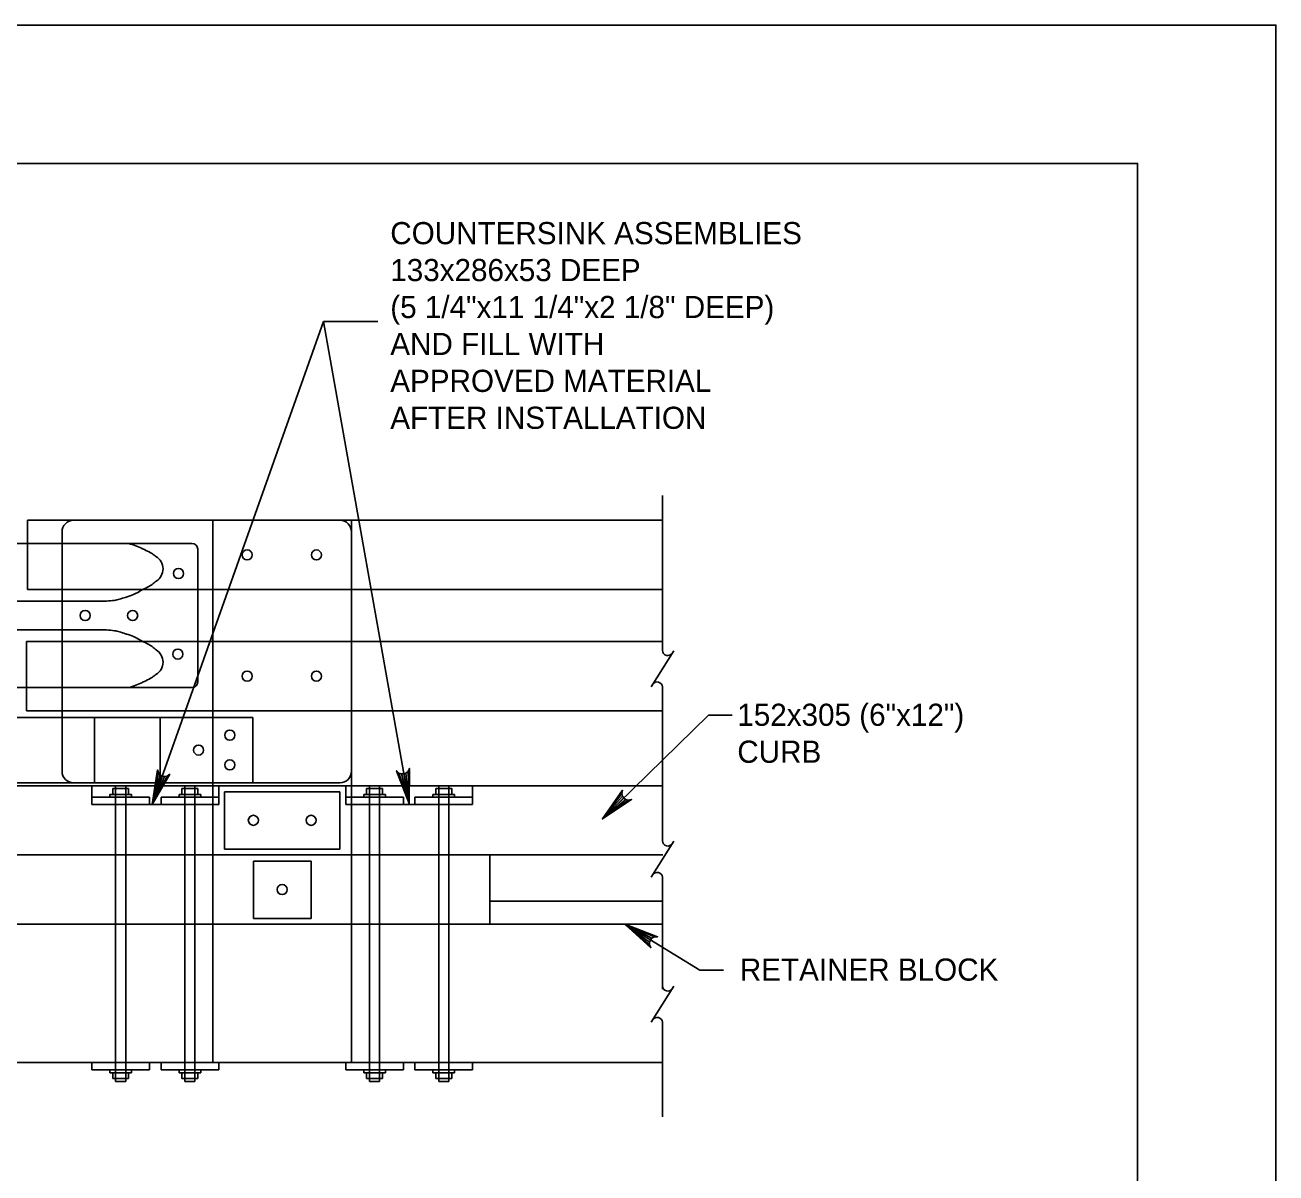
# Model space of a CAD drawing. Extents: x 0 to 36.3, y -66 to 0.
# Drawn here: x 27.22 to 34, y -6.22 to 0 of the extents above; entities that cross this region are included whole.
import ezdxf

# ---------------------------------------------------------------- set-up
doc = ezdxf.new("R2010")
doc.units = 0
for name, color, linetype in [('1', 7, 'Continuous'), ('2', 7, 'Continuous'), ('3', 7, 'Continuous'), ('52', 7, 'Continuous'), ('62', 7, 'Continuous'), ('63', 7, 'Continuous')]:
    doc.layers.add(name, color=color, linetype=linetype)

msp = doc.modelspace()

# ---------------------------------------------------------------- linework, layer by layer
at = {"layer": '1'}
msp.add_lwpolyline([(1.75, -21.25), (33.25, -21.25), (33.25, -0.75), (1.75, -0.75)], close=True, dxfattribs=at)
at = {"layer": '2'}
for p, q in [((30.6771, -2.5474), (30.6771, -3.3866)), ((27.2378, -2.6827), (29.2847, -2.6827)), ((28.243, -2.6827), (28.243, -3.0577)), ((28.993, -2.6827), (28.993, -3.0577)), ((29.2847, -2.6827), (30.6789, -2.6827)), ((27.4253, -2.7452), (27.4253, -3.5889)), ((26.2853, -2.8077), (28.1291, -2.8077)), ((27.2378, -2.8077), (27.2378, -3.0577)), ((28.1603, -2.839), (28.1603, -3.5577)), ((28.993, -3.0577), (27.2378, -3.0577)), ((28.243, -3.0577), (28.243, -3.3389)), ((28.993, -3.0577), (28.993, -3.3389)), ((28.993, -3.0577), (30.6789, -3.0577)), ((24.7539, -3.1202), (27.667, -3.1202)), ((24.7335, -3.2764), (27.667, -3.2764)), ((28.993, -3.3389), (27.2335, -3.3389)), ((27.2335, -3.5889), (27.2335, -3.3389)), ((28.243, -3.3389), (28.243, -3.7139)), ((28.993, -3.3389), (28.993, -3.7139)), ((28.993, -3.3389), (30.6789, -3.3389)), ((30.7385, -3.3888), (30.6157, -3.5844)), ((24.7335, -3.5889), (28.1291, -3.5889)), ((27.2335, -3.5889), (27.2335, -3.7139)), ((27.4253, -3.5889), (27.4253, -4.0414)), ((30.677, -3.584), (30.677, -4.4181)), ((27.2335, -3.7139), (27.4253, -3.7139)), ((28.993, -3.7139), (27.4253, -3.7139)), ((28.243, -3.7139), (28.243, -4.2217)), ((28.993, -3.7139), (28.993, -4.2217)), ((28.993, -3.7139), (30.6789, -3.7139)), ((24.5044, -3.7502), (28.459, -3.7502)), ((28.993, -3.9997), (28.993, -4.1202)), ((24.5044, -4.1039), (28.9305, -4.1039)), ((25.5295, -4.1202), (30.6789, -4.1202)), ((26.7773, -4.1202), (30.4587, -4.1202)), ((27.5867, -4.1202), (27.5867, -4.2217)), ((27.7156, -4.1202), (27.7703, -4.1202)), ((27.7156, -4.1202), (27.7156, -5.7217)), ((27.7703, -4.1202), (27.7703, -5.7217)), ((28.0906, -4.1202), (28.1453, -4.1202)), ((28.0906, -4.1202), (28.0906, -5.7217)), ((28.1453, -4.1202), (28.1453, -5.7217)), ((28.243, -4.1039), (28.243, -4.1202)), ((28.2742, -4.1202), (28.2742, -4.2217)), ((28.9617, -4.1202), (28.9617, -4.2217)), ((28.993, -4.1039), (28.993, -4.1697)), ((29.0906, -4.1202), (29.1453, -4.1202)), ((29.0906, -4.1202), (29.0906, -5.7217)), ((29.1453, -4.1202), (29.1453, -5.7217)), ((29.4656, -4.1202), (29.5203, -4.1202)), ((29.4656, -4.1202), (29.4656, -5.7217)), ((29.5203, -4.1202), (29.5203, -5.7217)), ((29.6492, -4.1202), (29.6492, -4.2217)), ((27.8992, -4.1827), (27.5867, -4.1827)), ((27.6843, -4.167), (27.6843, -4.1827)), ((27.6843, -4.167), (27.8015, -4.167)), ((27.6999, -4.1357), (27.6999, -4.167)), ((27.6999, -4.1357), (27.7859, -4.1357)), ((27.7859, -4.1357), (27.7859, -4.167)), ((27.8015, -4.167), (27.8015, -4.1827)), ((27.8992, -4.1827), (27.8992, -4.2217)), ((28.2742, -4.1827), (27.9617, -4.1827)), ((27.9617, -4.1827), (27.9617, -4.2217)), ((28.0593, -4.167), (28.0593, -4.1827)), ((28.0593, -4.167), (28.1765, -4.167)), ((28.0749, -4.1357), (28.1609, -4.1357)), ((28.0749, -4.1357), (28.0749, -4.167)), ((28.1609, -4.1357), (28.1609, -4.167)), ((28.1765, -4.167), (28.1765, -4.1827)), ((28.3055, -4.1537), (28.9305, -4.1537)), ((28.3055, -4.1537), (28.3055, -4.4639)), ((28.3055, -4.1538), (28.9305, -4.1538)), ((28.9305, -4.1537), (28.9305, -4.4639)), ((29.2742, -4.1827), (28.9617, -4.1827)), ((29.0593, -4.167), (29.0593, -4.1827)), ((29.0593, -4.167), (29.1765, -4.167)), ((29.0749, -4.1357), (29.1609, -4.1357)), ((29.0749, -4.1357), (29.0749, -4.167)), ((29.1609, -4.1357), (29.1609, -4.167)), ((29.1765, -4.167), (29.1765, -4.1827)), ((29.2742, -4.1827), (29.2742, -4.2217)), ((29.6492, -4.1827), (29.3367, -4.1827)), ((29.3367, -4.1827), (29.3367, -4.2217)), ((29.4343, -4.167), (29.4343, -4.1827)), ((29.4343, -4.167), (29.5515, -4.167)), ((29.4499, -4.1357), (29.5359, -4.1357)), ((29.4499, -4.1357), (29.4499, -4.167)), ((29.5359, -4.1357), (29.5359, -4.167)), ((29.5515, -4.167), (29.5515, -4.1827)), ((27.5867, -4.2217), (28.2742, -4.2217)), ((28.243, -4.2217), (28.243, -5.6201)), ((28.9617, -4.2217), (29.6492, -4.2217)), ((28.993, -4.2217), (28.993, -5.6201)), ((28.3055, -4.4639), (28.9305, -4.4639)), ((30.7385, -4.4203), (30.6157, -4.6159)), ((25.5295, -4.4952), (30.6789, -4.4952)), ((28.4617, -4.5287), (28.4617, -4.8389)), ((28.4617, -4.5287), (28.7742, -4.5287)), ((28.7742, -4.5287), (28.7742, -4.8389)), ((29.743, -4.4952), (29.743, -4.8702)), ((30.677, -4.6156), (30.677, -5.2228)), ((29.743, -4.7452), (30.6789, -4.7452)), ((25.5295, -4.8702), (30.6789, -4.8702)), ((28.4617, -4.8389), (28.7742, -4.8389)), ((30.7385, -5.2059), (30.6157, -5.4015)), ((30.677, -5.4023), (30.677, -5.9131)), ((25.5295, -5.6201), (30.6789, -5.6201)), ((27.5867, -5.6592), (27.5867, -5.6201)), ((27.8992, -5.6592), (27.8992, -5.6201)), ((27.9617, -5.6592), (27.9617, -5.6201)), ((28.2742, -5.6592), (28.2742, -5.6201)), ((28.9617, -5.6592), (28.9617, -5.6201)), ((29.2742, -5.6592), (29.2742, -5.6201)), ((29.3367, -5.6592), (29.3367, -5.6201)), ((29.6492, -5.6592), (29.6492, -5.6201)), ((27.8992, -5.6592), (27.5867, -5.6592)), ((27.6843, -5.6748), (27.6843, -5.6592)), ((27.6843, -5.6748), (27.8015, -5.6748)), ((27.6999, -5.7061), (27.6999, -5.6748)), ((27.7859, -5.7061), (27.7859, -5.6748)), ((27.8015, -5.6748), (27.8015, -5.6592)), ((28.2742, -5.6592), (27.9617, -5.6592)), ((28.0593, -5.6748), (28.0593, -5.6592)), ((28.0593, -5.6748), (28.1765, -5.6748)), ((28.0749, -5.7061), (28.0749, -5.6748)), ((28.1609, -5.7061), (28.1609, -5.6748)), ((28.1765, -5.6748), (28.1765, -5.6592)), ((29.2742, -5.6592), (28.9617, -5.6592)), ((29.0593, -5.6748), (29.0593, -5.6592)), ((29.0593, -5.6748), (29.1765, -5.6748)), ((29.0749, -5.7061), (29.0749, -5.6748)), ((29.1609, -5.7061), (29.1609, -5.6748)), ((29.1765, -5.6748), (29.1765, -5.6592)), ((29.6492, -5.6592), (29.3367, -5.6592)), ((29.4343, -5.6748), (29.4343, -5.6592)), ((29.4343, -5.6748), (29.5515, -5.6748)), ((29.4499, -5.7061), (29.4499, -5.6748)), ((29.5359, -5.7061), (29.5359, -5.6748)), ((29.5515, -5.6748), (29.5515, -5.6592)), ((27.6999, -5.7061), (27.7859, -5.7061)), ((27.7156, -5.7217), (27.7703, -5.7217)), ((28.0749, -5.7061), (28.1609, -5.7061)), ((28.0906, -5.7217), (28.1453, -5.7217)), ((29.0749, -5.7061), (29.1609, -5.7061)), ((29.0906, -5.7217), (29.1453, -5.7217)), ((29.4499, -5.7061), (29.5359, -5.7061)), ((29.4656, -5.7217), (29.5203, -5.7217))]:
    msp.add_line(p, q, dxfattribs=at)
for centre in [(28.4279, -2.8702), (28.8031, -2.8702), (28.0561, -2.9709), (27.5508, -3.1983), (27.8078, -3.1983), (28.0529, -3.4071), (28.4279, -3.5265), (28.8031, -3.5265), (28.3342, -3.8464), (28.165, -3.927), (28.3342, -4.0077), (28.4617, -4.3076), (28.7742, -4.3076), (28.618, -4.6826)]:
    msp.add_circle(centre, 0.0273, dxfattribs=at)
for centre, radius, start, end in [((27.4878, -2.7452), 0.0625, 90, 180), ((27.5337, -3.6302), 0.8602, 71.50655, 72.97663), ((27.756, -2.9656), 0.1594, 68.09066, 71.50655), ((25.7728, -7.8966), 5.4742, 67.68511, 68.09066), ((27.6609, -3.2963), 0.5016, 66.34532, 67.68511), ((27.7801, -3.0241), 0.2044, 63.42506, 66.34532), ((26.6682, -5.2469), 2.6898, 62.62019, 63.42506), ((28.129, -2.839), 0.0312, 0, 90), ((27.8681, -2.9302), 0.0808, 54.67713, 62.62019), ((27.6988, -3.169), 0.3735, 50.98486, 54.67712), ((27.8948, -2.9456), 0.0775, 301.3851, 59.64679), ((12.0358, 26.154), 33.224, 298.47252, 298.525), ((27.8577, -2.9561), 0.092, 298.525, 306.88177), ((27.6621, -2.6954), 0.4179, 306.88177, 310.79926), ((27.6474, -2.6951), 0.4255, 272.64288, 278.36698), ((27.6827, -2.9355), 0.1825, 278.36698, 287.11147), ((25.448, 4.3233), 7.7775, 287.11147, 287.36106), ((27.6895, -2.8462), 0.2658, 287.36106, 288.71113), ((27.2816, -1.6421), 1.5372, 288.71113, 290.23288), ((27.7944, -3.0333), 0.0545, 290.23288, 298.32146), ((26.9595, -1.4842), 1.8143, 298.32146, 298.75012), ((32.5137, -11.608), 9.733, 118.56505, 118.75012), ((32.9699, -12.4459), 10.6871, 118.47252, 118.56505), ((27.6474, -3.7015), 0.4255, 81.63302, 87.35713), ((27.6827, -3.4611), 0.1825, 72.88853, 81.63302), ((25.448, -10.7199), 7.7775, 72.63894, 72.88853), ((27.6895, -3.5504), 0.2658, 71.28887, 72.63894), ((27.2816, -4.7546), 1.5372, 69.76712, 71.28887), ((27.7944, -3.3634), 0.0545, 61.67854, 69.76712), ((26.9595, -4.9125), 1.8143, 61.24988, 61.67854), ((32.5137, 5.2113), 9.733, 241.24988, 241.43495), ((32.9699, 6.0493), 10.6871, 241.43495, 241.52748), ((12.0358, -32.5506), 33.224, 61.475, 61.52748), ((27.8577, -3.4405), 0.092, 53.11823, 61.475), ((27.6621, -3.7012), 0.4179, 49.20074, 53.11823), ((27.8948, -3.451), 0.0775, 300.35321, 58.61491), ((30.7059, -3.3866), 0.0289, 180, 330), ((27.6988, -3.2276), 0.3735, 305.32288, 309.01514), ((27.5337, -2.7665), 0.8602, 287.02337, 288.49345), ((27.756, -3.4311), 0.1594, 288.49345, 291.90934), ((25.7728, 1.4999), 5.4742, 291.90934, 292.31489), ((27.6609, -3.1003), 0.5016, 292.31489, 293.65468), ((27.7801, -3.3726), 0.2044, 293.65468, 296.57494), ((26.6682, -1.1498), 2.6898, 296.57494, 297.37981), ((27.8681, -3.4665), 0.0808, 297.37981, 305.32288), ((28.129, -3.5577), 0.0312, 270, 0), ((30.6483, -3.5867), 0.0289, 5.32859, 147.86724), ((27.4878, -4.0414), 0.0625, 180, 270), ((28.9304, -4.0414), 0.0625, 270, 0), ((30.7059, -4.4181), 0.0289, 180, 330), ((30.6483, -4.6182), 0.0289, 5.32859, 147.86724), ((30.7059, -5.2037), 0.0289, 180, 330), ((30.6483, -5.4037), 0.0289, 5.32859, 147.86724)]:
    msp.add_arc(centre, radius, start, end, dxfattribs=at)
at = {"layer": '3'}
for p, q in [((28.8409, -1.606), (27.9137, -4.2217)), ((28.8409, -1.606), (29.135, -1.606)), ((28.8409, -1.606), (29.3046, -4.2164)), ((27.2378, -2.6827), (27.2378, -2.8077)), ((28.993, -4.0414), (28.993, -2.7452)), ((27.601, -4.1039), (27.601, -3.7502)), ((27.9577, -4.1039), (27.9577, -3.7502)), ((28.459, -4.1039), (28.459, -3.7502))]:
    msp.add_line(p, q, dxfattribs=at)
for points in [[(27.9138, -4.2217), (27.9431, -4.0343), (27.9477, -4.0512), (27.9569, -4.0623), (27.968, -4.0685), (27.9805, -4.0707), (27.9947, -4.0678), (28.0089, -4.0577), (27.9138, -4.2217), (27.9947, -4.0678), (27.9805, -4.0707), (27.9138, -4.2217), (27.968, -4.0685), (27.9569, -4.0623), (27.9138, -4.2217), (27.9477, -4.0512)], [(29.3047, -4.2164), (29.2377, -4.039), (29.2499, -4.0514), (29.2636, -4.0565), (29.2762, -4.0564), (29.2882, -4.0521), (29.2992, -4.0427), (29.3065, -4.0267), (29.3047, -4.2164), (29.2992, -4.0427), (29.2882, -4.0521), (29.3047, -4.2164), (29.2762, -4.0564), (29.2636, -4.0565), (29.3047, -4.2164), (29.2499, -4.0514)]]:
    msp.add_lwpolyline(points, dxfattribs=at)
msp.add_arc((28.9304, -2.7452), 0.0625, 0, 90, dxfattribs=at)
at = {"layer": '52'}
for points in [[(30.3518, -4.3003), (30.9265, -3.7387), (31.055, -3.7387)], [(30.3518, -4.3003), (30.4607, -4.145), (30.4574, -4.1622), (30.4609, -4.1763), (30.4681, -4.1867), (30.4783, -4.1942), (30.4924, -4.1979), (30.5096, -4.195), (30.3518, -4.3003), (30.4924, -4.1979), (30.4783, -4.1942), (30.3518, -4.3003), (30.4681, -4.1867), (30.4609, -4.1763), (30.3518, -4.3003), (30.4574, -4.1622)], [(30.4735, -4.8702), (30.8792, -5.119), (31.0077, -5.119)], [(30.4736, -4.8702), (30.6507, -4.9378), (30.6333, -4.9388), (30.6204, -4.9456), (30.6121, -4.9552), (30.6073, -4.9669), (30.6072, -4.9814), (30.6142, -4.9974), (30.4736, -4.8702), (30.6072, -4.9814), (30.6073, -4.9669), (30.4736, -4.8702), (30.6121, -4.9552), (30.6204, -4.9456), (30.4736, -4.8702), (30.6333, -4.9388)]]:
    msp.add_lwpolyline(points, dxfattribs=at)
at = {"layer": '62'}
msp.add_line((34, 0), (34, 0), dxfattribs=at)
at = {"layer": '63'}
msp.add_lwpolyline([(0, -22), (34, -22), (34, 0), (0, 0)], close=True, dxfattribs=at)

# ---------------------------------------------------------------- texts
at = {"layer": '3'}
for s, p in [('COUNTERSINK ASSEMBLIES', (29.2032, -1.1872)), ('133x286x53 DEEP', (29.2032, -1.3872)), ('(5 1/4"x11 1/4"x2 1/8" DEEP)', (29.2032, -1.5873)), ('AND FILL WITH', (29.2032, -1.7873)), ('APPROVED MATERIAL', (29.2032, -1.9872)), ('AFTER INSTALLATION', (29.2032, -2.1873)), ('152x305 (6"x12")', (31.0826, -3.7959)), ('CURB', (31.0826, -3.9959)), ('RETAINER BLOCK', (31.0964, -5.176))]:
    msp.add_text(s, height=0.12, dxfattribs=at).set_placement(p)

doc.saveas('drawing.dxf')
